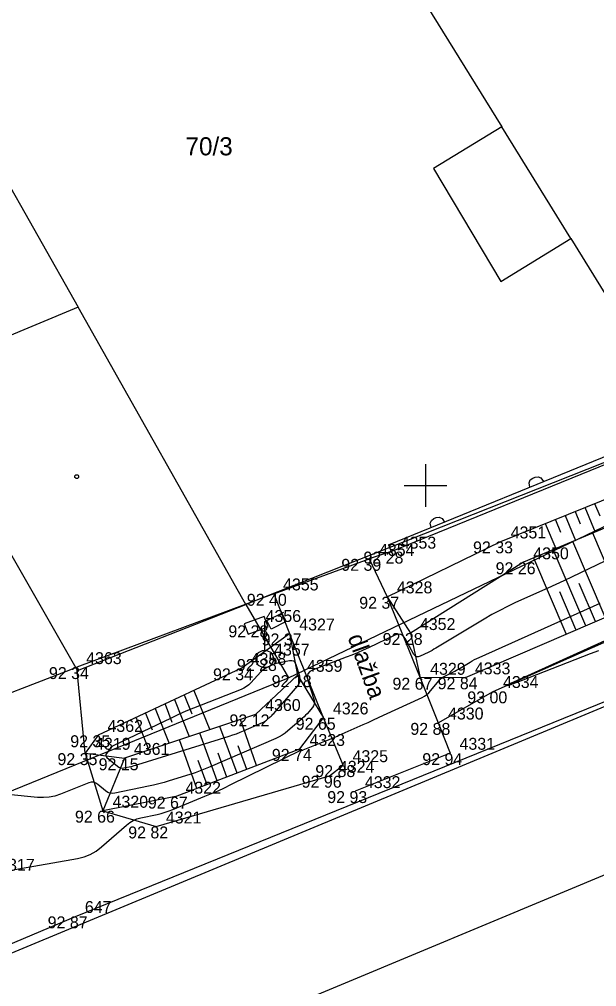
# Model space of a CAD drawing. Extents: x -711081 to -709338, y -1025122 to -1024092.
# Drawn here: x -709934.53 to -709920.98, y -1024586.76 to -1024564.06 of the extents above; entities that cross this region are included whole.
import ezdxf

# ---------------------------------------------------------------- set-up
doc = ezdxf.new("R2010")
doc.units = 0
for name, color, linetype in [('Ex_Major Contours', 7, 'Continuous'), ('Ex_Minor Contours', 7, 'Continuous'), ('Z_body', 7, 'Continuous'), ('Z_body_cisla', 7, 'Continuous'), ('Z_body_vysky_redukovane', 7, 'Continuous'), ('Z_budova', 7, 'Continuous'), ('Z_hektometricka_sit', 7, 'Continuous'), ('Z_hrany_paty', 7, 'Continuous'), ('Z_katastr_cisla_pozemkova', 7, 'Continuous'), ('Z_katastr_hranice', 7, 'Continuous'), ('Z_katastr_vnitrni_kresba', 7, 'Continuous'), ('Z_katastr_znacky_budov', 7, 'Continuous'), ('Z_komunikace', 7, 'Continuous'), ('Z_komunikace_osa', 7, 'Continuous'), ('Z_pilire', 7, 'Continuous'), ('Z_ploty', 7, 'Continuous'), ('Z_ploty_znacky', 7, 'Continuous'), ('Z_popisy', 7, 'Continuous'), ('Z_rozhranni', 7, 'Continuous'), ('Z_site_vo_znaky', 7, 'Continuous'), ('Z_technicke_srafy', 7, 'Continuous'), ('Z_vstupy', 7, 'Continuous')]:
    doc.layers.add(name, color=color, linetype=linetype)

# ---------------------------------------------------------------- blocks, each defined once
blk = doc.blocks.new('POINT_DISPLAY')
blk.add_line((0, 0), (0, 0))
blk = doc.blocks.new('Z666')
for p, q in [((-0.25, 0.13), (-0.25, -0.13)), ((0.25, 0.13), (-0.25, 0.13)), ((0.25, -0.13), (0.25, 0.13)), ((-0.25, -0.13), (0.25, -0.13))]:
    blk.add_line(p, q)
blk = doc.blocks.new('Z216')
for p, q in [((-0.17, 0), (-0.15, 0.1)), ((-0.15, 0.1), (-0.1, 0.15)), ((-0.1, 0.15), (-0.03, 0.17)), ((-0.03, 0.17), (0.03, 0.17)), ((0.03, 0.17), (0.1, 0.15)), ((0.1, 0.15), (0.15, 0.1)), ((0.15, 0.1), (0.17, 0))]:
    blk.add_line(p, q)
blk = doc.blocks.new('Z13')
for p, q in [((0, 0.88), (0.45, 1.1)), ((0.4, 1.07), (0.5, 0.88)), ((0, 0.2), (0, 0.88)), ((0.15, 0.7), (0.05, 0.9)), ((0.5, 0.88), (0.15, 0.7)), ((-0.2, 0.05), (-0.15, 0.15)), ((-0.2, -0.05), (-0.2, 0.05)), ((-0.15, 0.15), (-0.05, 0.2)), ((-0.05, 0.2), (0.05, 0.2)), ((0.05, 0.2), (0.15, 0.15)), ((0.15, 0.15), (0.2, 0.05)), ((0.2, 0.05), (0.2, -0.05)), ((-0.15, -0.15), (-0.2, -0.05)), ((-0.05, -0.2), (-0.15, -0.15)), ((0.05, -0.2), (-0.05, -0.2)), ((0.15, -0.15), (0.05, -0.2)), ((0.2, -0.05), (0.15, -0.15))]:
    blk.add_line(p, q)

msp = doc.modelspace()

# ---------------------------------------------------------------- linework, layer by layer
at = {"layer": 'Ex_Major Contours'}
msp.add_lwpolyline([(-709920.222, -1024578.383), (-709922.759, -1024579.534), (-709923.002, -1024579.648), (-709923.08, -1024579.691), (-709922.994, -1024579.666), (-709922.743, -1024579.571), (-709921.125, -1024578.943), (-709920.933, -1024578.874)], dxfattribs=at)
at = {"layer": 'Ex_Minor Contours'}
for points in [[(-709919.99, -1024576.39), (-709921.374, -1024577.056), (-709921.561, -1024577.145), (-709921.749, -1024577.234), (-709921.938, -1024577.321), (-709922.127, -1024577.406), (-709922.884, -1024577.747), (-709923.072, -1024577.835), (-709923.257, -1024577.928), (-709923.439, -1024578.027), (-709923.619, -1024578.131), (-709924.753, -1024578.814), (-709924.799, -1024578.841), (-709924.844, -1024578.867), (-709924.891, -1024578.891), (-709924.937, -1024578.915), (-709925.126, -1024579.006), (-709925.17, -1024579.021), (-709925.209, -1024579.018), (-709925.243, -1024578.998), (-709925.271, -1024578.961), (-709925.477, -1024578.588), (-709925.524, -1024578.525), (-709925.58, -1024578.491), (-709925.646, -1024578.486), (-709925.721, -1024578.51), (-709926.334, -1024578.805), (-709926.464, -1024578.865), (-709926.594, -1024578.923), (-709926.726, -1024578.977), (-709926.859, -1024579.029), (-709927.637, -1024579.321), (-709927.713, -1024579.362), (-709927.758, -1024579.419), (-709927.774, -1024579.489), (-709927.76, -1024579.575), (-709927.614, -1024580.037), (-709927.605, -1024580.083), (-709927.608, -1024580.126), (-709927.623, -1024580.167), (-709927.649, -1024580.205), (-709927.778, -1024580.353), (-709927.811, -1024580.39), (-709927.845, -1024580.425), (-709927.881, -1024580.459), (-709927.917, -1024580.492), (-709928.225, -1024580.757), (-709928.291, -1024580.809), (-709928.359, -1024580.856), (-709928.431, -1024580.897), (-709928.507, -1024580.933), (-709930.049, -1024581.602), (-709930.166, -1024581.651), (-709930.284, -1024581.697), (-709930.404, -1024581.74), (-709930.525, -1024581.779), (-709931.01, -1024581.93), (-709931.131, -1024581.966), (-709931.254, -1024582), (-709931.377, -1024582.03), (-709931.501, -1024582.057), (-709932.291, -1024582.22), (-709932.349, -1024582.226), (-709932.404, -1024582.219), (-709932.455, -1024582.199), (-709932.503, -1024582.166), (-709932.689, -1024582.011), (-709932.736, -1024581.98), (-709932.787, -1024581.964), (-709932.839, -1024581.963), (-709932.894, -1024581.978), (-709933.563, -1024582.242), (-709933.695, -1024582.285), (-709933.828, -1024582.312), (-709933.964, -1024582.323), (-709934.103, -1024582.318), (-709935.578, -1024582.173)], [(-709934.634, -1024584.013), (-709933.164, -1024583.75), (-709933.009, -1024583.712), (-709932.863, -1024583.654), (-709932.727, -1024583.576), (-709932.6, -1024583.479), (-709932.014, -1024582.966), (-709931.937, -1024582.908), (-709931.856, -1024582.86), (-709931.769, -1024582.823), (-709931.676, -1024582.797), (-709931.296, -1024582.715), (-709931.201, -1024582.692), (-709931.108, -1024582.665), (-709931.016, -1024582.634), (-709930.925, -1024582.599), (-709930.174, -1024582.292), (-709930.02, -1024582.227), (-709929.866, -1024582.16), (-709929.714, -1024582.09), (-709929.563, -1024582.017), (-709927.927, -1024581.213), (-709927.923, -1024581.211), (-709927.918, -1024581.21), (-709927.913, -1024581.209), (-709927.908, -1024581.208), (-709927.887, -1024581.208), (-709927.882, -1024581.207), (-709927.877, -1024581.206), (-709927.872, -1024581.205), (-709927.868, -1024581.203), (-709927.362, -1024581.001), (-709927.276, -1024580.967), (-709927.191, -1024580.931), (-709927.106, -1024580.895), (-709927.021, -1024580.858), (-709926.463, -1024580.61), (-709926.342, -1024580.556), (-709926.221, -1024580.501), (-709926.1, -1024580.446), (-709925.98, -1024580.39), (-709925.08, -1024579.97), (-709925.022, -1024579.939), (-709924.969, -1024579.902), (-709924.92, -1024579.86), (-709924.875, -1024579.812), (-709924.684, -1024579.581), (-709924.651, -1024579.545), (-709924.615, -1024579.513), (-709924.575, -1024579.486), (-709924.533, -1024579.462), (-709924.356, -1024579.376), (-709924.312, -1024579.354), (-709924.268, -1024579.331), (-709924.225, -1024579.307), (-709924.183, -1024579.282), (-709923.954, -1024579.144), (-709923.901, -1024579.113), (-709923.847, -1024579.084), (-709923.793, -1024579.057), (-709923.738, -1024579.031), (-709920.903, -1024577.756)]]:
    msp.add_lwpolyline(points, dxfattribs=at)
msp.add_lwpolyline([(-709929.146, -1024579.676), (-709929.2, -1024579.718), (-709929.259, -1024579.754), (-709929.322, -1024579.783), (-709930.265, -1024580.15), (-709930.443, -1024580.221), (-709930.62, -1024580.296), (-709930.796, -1024580.374), (-709930.969, -1024580.456), (-709932.312, -1024581.102), (-709932.34, -1024581.118), (-709932.365, -1024581.136), (-709932.387, -1024581.158), (-709932.408, -1024581.183), (-709932.483, -1024581.288), (-709932.496, -1024581.313), (-709932.498, -1024581.337), (-709932.49, -1024581.36), (-709932.471, -1024581.381), (-709932.225, -1024581.587), (-709932.191, -1024581.61), (-709932.156, -1024581.623), (-709932.118, -1024581.628), (-709932.077, -1024581.624), (-709931.912, -1024581.59), (-709931.871, -1024581.581), (-709931.83, -1024581.571), (-709931.789, -1024581.56), (-709931.749, -1024581.548), (-709929.604, -1024580.88), (-709929.518, -1024580.852), (-709929.434, -1024580.822), (-709929.35, -1024580.789), (-709929.267, -1024580.755), (-709928.825, -1024580.563), (-709928.799, -1024580.55), (-709928.774, -1024580.536), (-709928.751, -1024580.52), (-709928.728, -1024580.502), (-709928.641, -1024580.427), (-709928.62, -1024580.408), (-709928.599, -1024580.388), (-709928.579, -1024580.368), (-709928.56, -1024580.346), (-709927.997, -1024579.7), (-709927.961, -1024579.648), (-709927.941, -1024579.592), (-709927.937, -1024579.534), (-709927.949, -1024579.471), (-709928.034, -1024579.203), (-709928.057, -1024579.155), (-709928.09, -1024579.123), (-709928.134, -1024579.109), (-709928.187, -1024579.113), (-709928.465, -1024579.169), (-709928.502, -1024579.178), (-709928.538, -1024579.188), (-709928.573, -1024579.201), (-709928.607, -1024579.216), (-709928.743, -1024579.281), (-709928.776, -1024579.299), (-709928.807, -1024579.32), (-709928.836, -1024579.343), (-709928.862, -1024579.37), (-709929.096, -1024579.627)], close=True, dxfattribs=at)
at = {"layer": 'Z_budova'}
for p, q in [((-709925.87, -1024576.39), (-709925.8, -1024576.55)), ((-709925.8, -1024576.55), (-709926.32, -1024576.72)), ((-709928.56, -1024577.54), (-709933.18, -1024579.26))]:
    msp.add_line(p, q, dxfattribs=at)
at = {"layer": 'Z_hektometricka_sit'}
for p, q in [((-709925, -1024574.5), (-709925, -1024575.5)), ((-709925.5, -1024575), (-709924.5, -1024575))]:
    msp.add_line(p, q, dxfattribs=at)
at = {"layer": 'Z_hrany_paty'}
for p, q in [((-709923.23, -1024576.31), (-709919.71, -1024574.89)), ((-709919.61, -1024575.5), (-709922.7, -1024576.8)), ((-709925.9, -1024577.61), (-709923.23, -1024576.31)), ((-709922.7, -1024576.8), (-709925.35, -1024578.46)), ((-709925.9, -1024577.61), (-709925.35, -1024578.46)), ((-709924.06, -1024579.5), (-709920.32, -1024577.89)), ((-709925.35, -1024578.46), (-709925.12, -1024579.51)), ((-709929.33, -1024579.29), (-709928.19, -1024578.47)), ((-709928.19, -1024578.47), (-709928, -1024579.45)), ((-709929.33, -1024579.29), (-709932.68, -1024580.86)), ((-709928, -1024579.45), (-709928.99, -1024580.37)), ((-709928, -1024579.45), (-709927.39, -1024580.45)), ((-709924.06, -1024579.5), (-709925.12, -1024579.51)), ((-709928.99, -1024580.37), (-709932.06, -1024581.4)), ((-709927.95, -1024581.18), (-709927.39, -1024580.45)), ((-709932.68, -1024580.86), (-709932.98, -1024581.28)), ((-709930.86, -1024582.3), (-709927.95, -1024581.18)), ((-709932.98, -1024581.28), (-709932.06, -1024581.4)), ((-709932.06, -1024581.4), (-709932.57, -1024582.63)), ((-709930.86, -1024582.3), (-709932.57, -1024582.63))]:
    msp.add_line(p, q, dxfattribs=at)
at = {"layer": 'Z_katastr_hranice'}
for p, q in [((-709929.42, -1024556.5), (-709923.21, -1024566.58)), ((-709938.58, -1024561.23), (-709933.15, -1024570.81)), ((-709923.21, -1024566.58), (-709924.81, -1024567.56)), ((-709924.81, -1024567.56), (-709923.23, -1024570.21)), ((-709923.23, -1024570.21), (-709921.59, -1024569.2)), ((-709921.59, -1024569.2), (-709918.83, -1024573.68)), ((-709933.15, -1024570.81), (-709937.1, -1024572.47)), ((-709929.21, -1024577.79), (-709933.15, -1024570.81)), ((-709928.21, -1024579.51), (-709910.92, -1024571.21)), ((-709918.83, -1024573.68), (-709929.21, -1024577.79)), ((-709929.21, -1024577.79), (-709928.21, -1024579.51)), ((-709944.54, -1024586.17), (-709928.21, -1024579.51))]:
    msp.add_line(p, q, dxfattribs=at)
at = {"layer": 'Z_katastr_vnitrni_kresba'}
for p, q in [((-709940.71, -1024588.46), (-709879.87, -1024563.16)), ((-709921.59, -1024569.2), (-709923.21, -1024566.58)), ((-709933.16, -1024579.34), (-709937.1, -1024572.47)), ((-709933.16, -1024579.34), (-709929.21, -1024577.79))]:
    msp.add_line(p, q, dxfattribs=at)
at = {"layer": 'Z_katastr_znacky_budov'}
msp.add_circle((-709933.182, -1024574.79), 0.0437, dxfattribs=at)
at = {"layer": 'Z_komunikace'}
for p, q in [((-709933.21, -1024585.11), (-709914.6, -1024577.55)), ((-709946.68, -1024590.84), (-709933.21, -1024585.11))]:
    msp.add_line(p, q, dxfattribs=at)
at = {"layer": 'Z_komunikace_osa'}
msp.add_line((-709931.75, -1024588.7), (-709913.44, -1024581.06), dxfattribs=at)
at = {"layer": 'Z_ploty'}
for p, q in [((-709925.87, -1024576.39), (-709920.01, -1024574)), ((-709925.8, -1024576.55), (-709919.94, -1024574.16))]:
    msp.add_line(p, q, dxfattribs=at)
at = {"layer": 'Z_rozhranni'}
for p, q in [((-709926.32, -1024576.72), (-709925.9, -1024577.61)), ((-709928.56, -1024577.54), (-709928.19, -1024578.47)), ((-709925.9, -1024577.61), (-709925.12, -1024579.51)), ((-709923.41, -1024579.83), (-709920.13, -1024578.38)), ((-709927.39, -1024580.45), (-709928.19, -1024578.47)), ((-709932.98, -1024581.28), (-709933.18, -1024579.26)), ((-709925.12, -1024579.51), (-709924.7, -1024580.57)), ((-709924.7, -1024580.57), (-709923.41, -1024579.83)), ((-709926.93, -1024581.56), (-709927.39, -1024580.45)), ((-709924.7, -1024580.57), (-709924.42, -1024581.28)), ((-709932.98, -1024581.28), (-709932.57, -1024582.63)), ((-709924.42, -1024581.28), (-709926.65, -1024582.17)), ((-709927.25, -1024581.81), (-709926.93, -1024581.56)), ((-709931.32, -1024583), (-709927.25, -1024581.81)), ((-709932.57, -1024582.63), (-709931.32, -1024583))]:
    msp.add_line(p, q, dxfattribs=at)
at = {"layer": 'Z_technicke_srafy'}
for p, q in [((-709921.26, -1024575.51), (-709921.02, -1024576.09)), ((-709921.03, -1024575.42), (-709920.91, -1024575.71)), ((-709921.72, -1024575.7), (-709921.48, -1024576.29)), ((-709921.49, -1024575.61), (-709921.37, -1024575.9)), ((-709922.19, -1024575.89), (-709921.94, -1024576.48)), ((-709921.95, -1024575.8), (-709921.83, -1024576.09)), ((-709920.32, -1024577.89), (-709921.07, -1024576.12)), ((-709920.78, -1024578.09), (-709921.54, -1024576.31)), ((-709921.24, -1024578.29), (-709922, -1024576.5)), ((-709921.7, -1024578.48), (-709922.46, -1024576.7)), ((-709921.01, -1024578.19), (-709921.39, -1024577.3)), ((-709921.47, -1024578.38), (-709921.85, -1024577.49)), ((-709930.43, -1024579.81), (-709930.06, -1024580.73)), ((-709930.89, -1024580.02), (-709930.54, -1024580.89)), ((-709930.66, -1024579.91), (-709930.48, -1024580.36)), ((-709931.34, -1024580.23), (-709931.01, -1024581.05)), ((-709931.11, -1024580.13), (-709930.95, -1024580.55)), ((-709931.79, -1024580.45), (-709931.49, -1024581.21)), ((-709931.57, -1024580.34), (-709931.41, -1024580.73)), ((-709928.96, -1024581.57), (-709929.34, -1024580.49)), ((-709929.42, -1024581.75), (-709929.82, -1024580.65)), ((-709929.89, -1024581.93), (-709930.29, -1024580.81)), ((-709930.36, -1024582.11), (-709930.77, -1024580.97)), ((-709929.19, -1024581.66), (-709929.39, -1024581.11)), ((-709929.66, -1024581.84), (-709929.86, -1024581.28)), ((-709930.12, -1024582.02), (-709930.33, -1024581.45))]:
    msp.add_line(p, q, dxfattribs=at)
at = {"layer": 'Z_vstupy'}
for p, q in [((-709928.56, -1024577.54), (-709926.32, -1024576.72)), ((-709936.19, -1024580.43), (-709933.18, -1024579.26))]:
    msp.add_line(p, q, dxfattribs=at)

# ---------------------------------------------------------------- block references
at = {"layer": 'Z_body'}
for p in [(-709923.23, -1024576.31), (-709925.8, -1024576.55), (-709926.32, -1024576.72), (-709922.7, -1024576.8), (-709928.56, -1024577.54), (-709925.9, -1024577.61), (-709928.97, -1024578.28), (-709925.35, -1024578.46), (-709928.19, -1024578.47), (-709928.77, -1024579.07), (-709933.18, -1024579.26), (-709929.33, -1024579.29), (-709928, -1024579.45), (-709925.12, -1024579.51), (-709924.06, -1024579.5), (-709923.41, -1024579.83), (-709928.99, -1024580.37), (-709927.39, -1024580.45), (-709924.7, -1024580.57), (-709932.68, -1024580.86), (-709927.95, -1024581.18), (-709932.98, -1024581.28), (-709932.06, -1024581.4), (-709924.42, -1024581.28), (-709926.93, -1024581.56), (-709927.25, -1024581.81), (-709930.86, -1024582.3), (-709926.65, -1024582.17), (-709932.57, -1024582.63), (-709931.32, -1024583), (-709933.21, -1024585.11)]:
    msp.add_blockref('POINT_DISPLAY', p, dxfattribs=at)
at = {"layer": 'Z_pilire', "rotation": 20.7}
msp.add_blockref('Z666', (-709928.97, -1024578.28), dxfattribs=at)
at = {"layer": 'Z_ploty_znacky', "rotation": 22.2}
for p in [(-709922.39, -1024574.97), (-709924.71, -1024575.92)]:
    msp.add_blockref('Z216', p, dxfattribs=at)
at = {"layer": 'Z_site_vo_znaky'}
msp.add_blockref('Z13', (-709928.77, -1024579.07), dxfattribs=at)

# ---------------------------------------------------------------- texts
at = {"layer": 'Z_body_cisla'}
for s, p in [('4351', (-709923, -1024576.24)), ('4353', (-709925.58, -1024576.48)), ('4354', (-709926.09, -1024576.65)), ('4350', (-709922.47, -1024576.73)), ('4355', (-709928.34, -1024577.46)), ('4328', (-709925.67, -1024577.53)), ('4356', (-709928.75, -1024578.2)), ('4327', (-709927.96, -1024578.4)), ('4352', (-709925.13, -1024578.39)), ('4363', (-709932.96, -1024579.19)), ('4357', (-709928.55, -1024578.99)), ('4358', (-709929.1, -1024579.21)), ('4359', (-709927.78, -1024579.37)), ('4333', (-709923.84, -1024579.43)), ('4329', (-709924.89, -1024579.44)), ('4334', (-709923.18, -1024579.75)), ('4360', (-709928.76, -1024580.29)), ('4326', (-709927.17, -1024580.37)), ('4330', (-709924.47, -1024580.49)), ('4362', (-709932.46, -1024580.78)), ('4319', (-709932.75, -1024581.2)), ('4323', (-709927.72, -1024581.11)), ('4331', (-709924.2, -1024581.2)), ('4361', (-709931.84, -1024581.32)), ('4325', (-709926.71, -1024581.49)), ('4324', (-709927.03, -1024581.74)), ('4332', (-709926.42, -1024582.1)), ('4322', (-709930.63, -1024582.23)), ('4320', (-709932.34, -1024582.56)), ('4321', (-709931.09, -1024582.93)), ('4317', (-709935, -1024584.04)), ('647', (-709932.99, -1024585.03))]:
    msp.add_text(s, height=0.28, dxfattribs=at).set_placement(p)
at = {"layer": 'Z_body_vysky_redukovane'}
for s, p in [('92 33', (-709923.883, -1024576.59)), ('92 28', (-709926.453, -1024576.83)), ('92 39', (-709926.973, -1024577)), ('92 26', (-709923.353, -1024577.08)), ('92 40', (-709929.19, -1024577.82)), ('92 37', (-709926.553, -1024577.89)), ('92 28', (-709929.623, -1024578.56)), ('92 37', (-709928.843, -1024578.75)), ('92 28', (-709926.003, -1024578.74)), ('92 28', (-709929.423, -1024579.35)), ('92 34', (-709933.833, -1024579.54)), ('92 34', (-709929.983, -1024579.57)), ('92 18', (-709928.607, -1024579.73)), ('92 67', (-709925.773, -1024579.79)), ('92 84', (-709924.713, -1024579.78)), ('93 00', (-709924.017, -1024580.11)), ('92 12', (-709929.597, -1024580.65)), ('92 65', (-709928.043, -1024580.73)), ('92 88', (-709925.353, -1024580.85)), ('92 35', (-709933.333, -1024581.14)), ('92 74', (-709928.603, -1024581.46)), ('92 35', (-709933.633, -1024581.56)), ('92 15', (-709932.667, -1024581.68)), ('92 94', (-709925.073, -1024581.56)), ('92 88', (-709927.583, -1024581.84)), ('92 96', (-709927.903, -1024582.09)), ('92 67', (-709931.513, -1024582.58)), ('92 93', (-709927.303, -1024582.45)), ('92 66', (-709933.223, -1024582.91)), ('92 82', (-709931.973, -1024583.28)), ('92 87', (-709933.863, -1024585.39))]:
    msp.add_text(s, height=0.28, dxfattribs=at).set_placement(p)
at = {"layer": 'Z_katastr_cisla_pozemkova'}
msp.add_text('70/3', height=0.425, dxfattribs=at).set_placement((-709930.628, -1024567.25))
at = {"layer": 'Z_popisy'}
msp.add_text('dlažba', height=0.4, rotation=289.8, dxfattribs=at).set_placement((-709926.83, -1024578.56))

doc.saveas('drawing.dxf')
